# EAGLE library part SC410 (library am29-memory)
ELAN SC410 embedded 486 processor
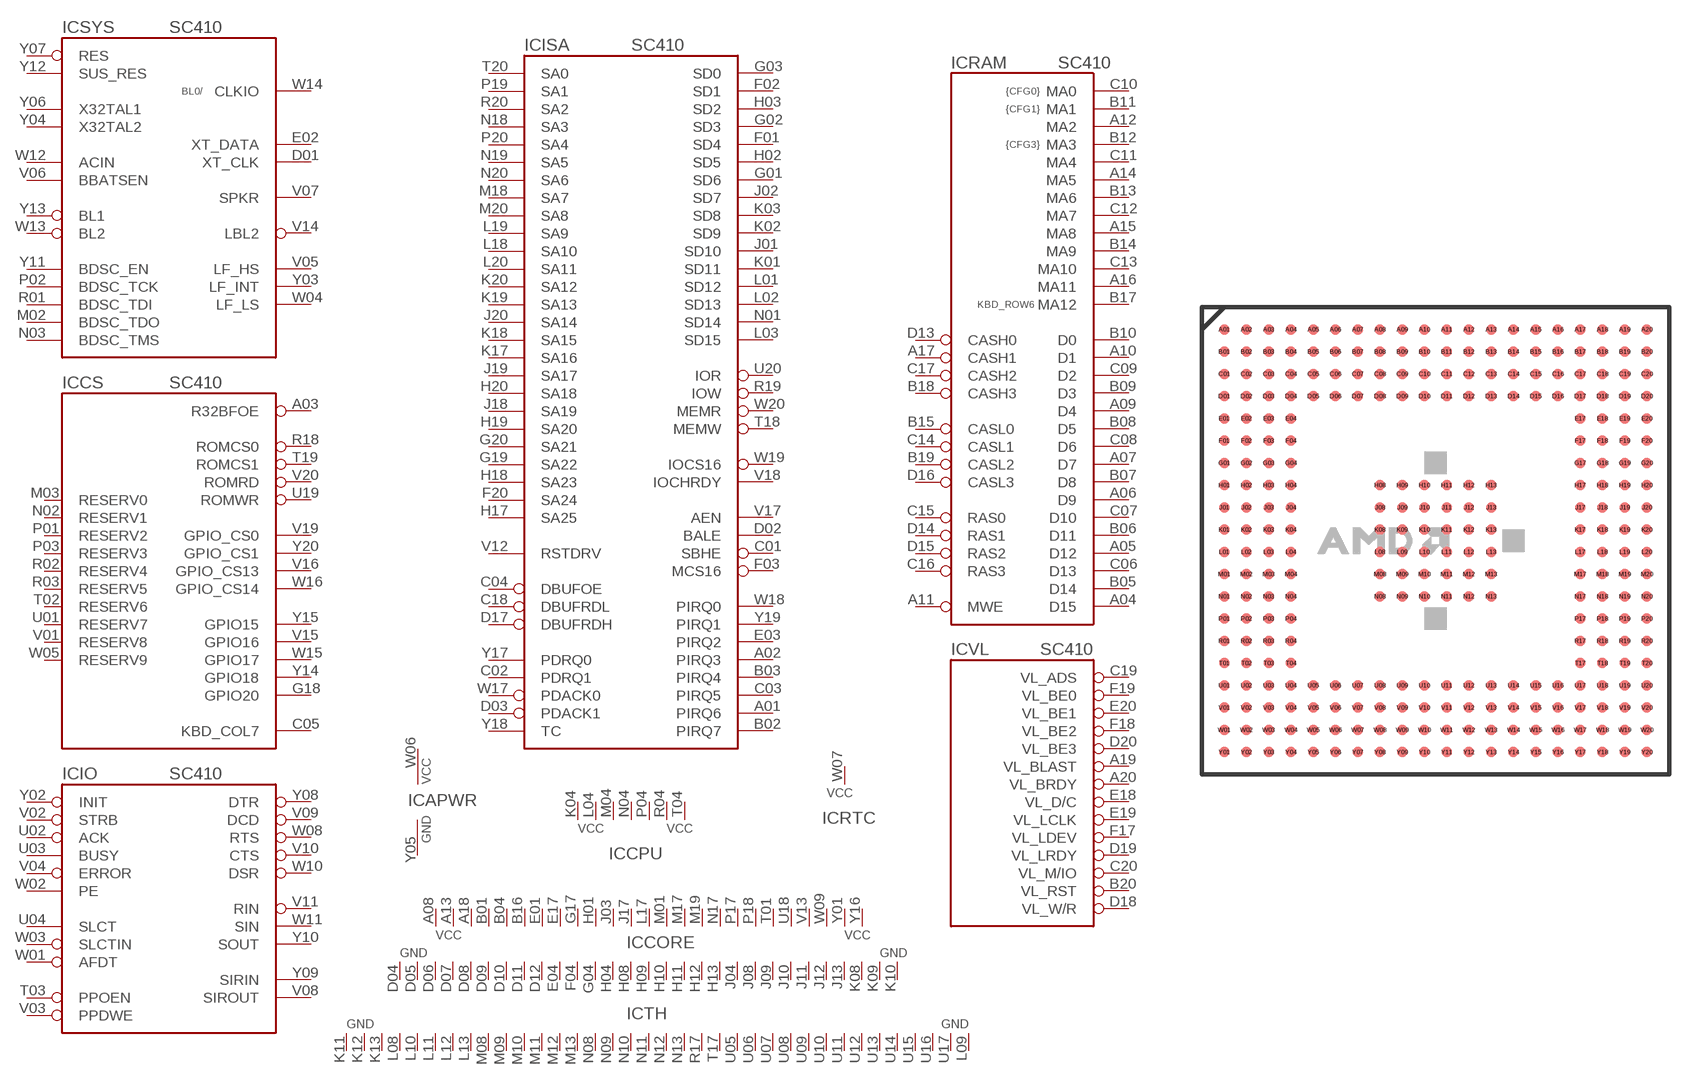
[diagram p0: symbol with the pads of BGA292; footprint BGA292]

Designator prefix IC; gates APWR=APWR CORE=COREPWR CPU=CPUPWR RTC=RTCPWR TH=THERM36 SYS=SYSMGR CS=CHIPSEL IO=SIO_EPP ISA=ISABUS RAM=DRAMBUS VL=VLBUS

## SC410  [BGA292]
A01  ISA:PIRQ6  in
A02  ISA:PIRQ3  in
A03  CS:R32BFOE  out
A04  RAM:D15
A05  RAM:D12
A06  RAM:D9
A07  RAM:D7
A08  CORE:VCC  pwr
A09  RAM:D4
A10  RAM:D1
A11  RAM:MWE  out
A12  RAM:MA2  out
A13  CORE:VCC  pwr
A14  RAM:MA5  out
A15  RAM:MA8  out
A16  RAM:MA11  out
A17  RAM:CASH1  out
A18  CORE:VCC  pwr
A19  VL:VL_BLAST  out
A20  VL:VL_BRDY  out
B01  CORE:VCC  pwr
B02  ISA:PIRQ7  in
B03  ISA:PIRQ4  in
B04  CORE:VCC  pwr
B05  RAM:D14
B06  RAM:D11
B07  RAM:D8
B08  RAM:D5
B09  RAM:D3
B10  RAM:D0
B11  RAM:MA1  out
B12  RAM:MA3  out
B13  RAM:MA6  out
B14  RAM:MA9  out
B15  RAM:CASL0  out
B16  CORE:VCC  pwr
B17  RAM:MA12  out
B18  RAM:CASH3  out
B19  RAM:CASL2  out
B20  VL:VL_RST  out
C01  ISA:SBHE  out
C02  ISA:PDRQ1  in
C03  ISA:PIRQ5  in
C04  ISA:DBUFOE  out
C05  CS:KBD_COL7  out
C06  RAM:D13
C07  RAM:D10
C08  RAM:D6
C09  RAM:D2
C10  RAM:MA0  out
C11  RAM:MA4  out
C12  RAM:MA7  out
C13  RAM:MA10  out
C14  RAM:CASL1  out
C15  RAM:RAS0  out
C16  RAM:RAS3  out
C17  RAM:CASH2  out
C18  ISA:DBUFRDL  out
C19  VL:VL_ADS  out
C20  VL:VL_M/IO  out
D01  SYS:XT_CLK
D02  ISA:BALE  out
D03  ISA:PDACK1  in
D04  CORE:GND  pwr
D05  CORE:GND  pwr
D06  CORE:GND  pwr
D07  CORE:GND  pwr
D08  CORE:GND  pwr
D09  CORE:GND  pwr
D10  CORE:GND  pwr
D11  CORE:GND  pwr
D12  CORE:GND  pwr
D13  RAM:CASH0  out
D14  RAM:RAS1  out
D15  RAM:RAS2  out
D16  RAM:CASL3  out
D17  ISA:DBUFRDH  out
D18  VL:VL_W/R  out
D19  VL:VL_LRDY  out
D20  VL:VL_BE3  out
E01  CORE:VCC  pwr
E02  SYS:XT_DATA
E03  ISA:PIRQ2  in
E04  CORE:GND  pwr
E17  CORE:VCC  pwr
E18  VL:VL_D/C  out
E19  VL:VL_LCLK  out
E20  VL:VL_BE1  out
F01  ISA:SD4
F02  ISA:SD1
F03  ISA:MCS16  out
F04  CORE:GND  pwr
F17  VL:VL_LDEV  out
F18  VL:VL_BE2  out
F19  VL:VL_BE0  out
F20  ISA:SA24  out
G01  ISA:SD6
G02  ISA:SD3
G03  ISA:SD0
G04  CORE:GND  pwr
G17  CORE:VCC  pwr
G18  CS:GPIO20  out
G19  ISA:SA22  out
G20  ISA:SA21  out
H01  CORE:VCC  pwr
H02  ISA:SD5
H03  ISA:SD2
H04  CORE:GND  pwr
H08  CORE:GND  pwr
H09  CORE:GND  pwr
H10  CORE:GND  pwr
H11  CORE:GND  pwr
H12  CORE:GND  pwr
H13  CORE:GND  pwr
H17  ISA:SA25  out
H18  ISA:SA23  out
H19  ISA:SA20  out
H20  ISA:SA18  out
J01  ISA:SD10
J02  ISA:SD7
J03  CORE:VCC  pwr
J04  CORE:GND  pwr
J08  CORE:GND  pwr
J09  CORE:GND  pwr
J10  CORE:GND  pwr
J11  CORE:GND  pwr
J12  CORE:GND  pwr
J13  CORE:GND  pwr
J17  CORE:VCC  pwr
J18  ISA:SA19  out
J19  ISA:SA17  out
J20  ISA:SA14  out
K01  ISA:SD11
K02  ISA:SD9
K03  ISA:SD8
K04  CPU:CPUVCC  pwr
K08  CORE:GND  pwr
K09  CORE:GND  pwr
K10  CORE:GND  pwr
K11  TH:GND  pwr
K12  TH:GND  pwr
K13  TH:GND  pwr
K17  ISA:SA16  out
K18  ISA:SA15  out
K19  ISA:SA13  out
K20  ISA:SA12  out
L01  ISA:SD12
L02  ISA:SD13
L03  ISA:SD15
L04  CPU:CPUVCC  pwr
L08  TH:GND  pwr
L09  TH:GND  pwr
L10  TH:GND  pwr
L11  TH:GND  pwr
L12  TH:GND  pwr
L13  TH:GND  pwr
L17  CORE:VCC  pwr
L18  ISA:SA10  out
L19  ISA:SA9  out
L20  ISA:SA11  out
M01  CORE:VCC  pwr
M02  SYS:BDSC_TDO  in
M03  CS:RESERV0  nc
M04  CPU:CPUVCC  pwr
M08  TH:GND  pwr
M09  TH:GND  pwr
M10  TH:GND  pwr
M11  TH:GND  pwr
M12  TH:GND  pwr
M13  TH:GND  pwr
M17  CORE:VCC  pwr
M18  ISA:SA7  out
M19  CORE:VCC  pwr
M20  ISA:SA8  out
N01  ISA:SD14
N02  CS:RESERV1  nc
N03  SYS:BDSC_TMS  in
N04  CPU:CPUVCC  pwr
N08  TH:GND  pwr
N09  TH:GND  pwr
N10  TH:GND  pwr
N11  TH:GND  pwr
N12  TH:GND  pwr
N13  TH:GND  pwr
N17  CORE:VCC  pwr
N18  ISA:SA3  out
N19  ISA:SA5  out
N20  ISA:SA6  out
P01  CS:RESERV2  nc
P02  SYS:BDSC_TCK  in
P03  CS:RESERV3  nc
P04  CPU:CPUVCC  pwr
P17  CORE:VCC  pwr
P18  CORE:VCC  pwr
P19  ISA:SA1  out
P20  ISA:SA4  out
R01  SYS:BDSC_TDI  in
R02  CS:RESERV4  nc
R03  CS:RESERV5  nc
R04  CPU:CPUVCC  pwr
R17  TH:GND  pwr
R18  CS:ROMCS0  out
R19  ISA:IOW  out
R20  ISA:SA2  out
T01  CORE:VCC  pwr
T02  CS:RESERV6  nc
T03  IO:PPOEN  out
T04  CPU:CPUVCC  pwr
T17  TH:GND  pwr
T18  ISA:MEMW  out
T19  CS:ROMCS1  out
T20  ISA:SA0  out
U01  CS:RESERV7  nc
U02  IO:ACK  in
U03  IO:BUSY  in
U04  IO:SLCT  in
U05  TH:GND  pwr
U06  TH:GND  pwr
U07  TH:GND  pwr
U08  TH:GND  pwr
U09  TH:GND  pwr
U10  TH:GND  pwr
U11  TH:GND  pwr
U12  TH:GND  pwr
U13  TH:GND  pwr
U14  TH:GND  pwr
U15  TH:GND  pwr
U16  TH:GND  pwr
U17  TH:GND  pwr
U18  CORE:VCC  pwr
U19  CS:ROMWR  out
U20  ISA:IOR  out
V01  CS:RESERV8  nc
V02  IO:STRB  out
V03  IO:PPDWE  out
V04  IO:ERROR  in
V05  SYS:LF_HS  out
V06  SYS:BBATSEN  in
V07  SYS:SPKR  out
V08  IO:SIROUT  out
V09  IO:DCD  in
V10  IO:CTS  out
V11  IO:RIN  in
V12  ISA:RSTDRV  out
V13  CORE:VCC  pwr
V14  SYS:LBL2  out
V15  CS:GPIO16  out
V16  CS:GPIO_CS13  out
V17  ISA:AEN  out
V18  ISA:IOCHRDY  in
V19  CS:GPIO_CS0  out
V20  CS:ROMRD  out
W01  IO:AFDT  out
W02  IO:PE  in
W03  IO:SLCTIN  out
W04  SYS:LF_LS  out
W05  CS:RESERV9  nc
W06  APWR:AVCC  pwr
W07  RTC:RTCVCC  pwr
W08  IO:RTS  out
W09  CORE:VCC  pwr
W10  IO:DSR  in
W11  IO:SIN  in
W12  SYS:ACIN  in
W13  SYS:BL2  in
W14  SYS:CLKIO
W15  CS:GPIO17  out
W16  CS:GPIO_CS14  out
W17  ISA:PDACK0  in
W18  ISA:PIRQ0  in
W19  ISA:IOCS16  in
W20  ISA:MEMR  out
Y01  CORE:VCC  pwr
Y02  IO:INIT  out
Y03  SYS:LF_INT  out
Y04  SYS:X32TAL2  in
Y05  APWR:AGND  pwr
Y06  SYS:X32TAL1  in
Y07  SYS:RES  in
Y08  IO:DTR  out
Y09  IO:SIRIN  in
Y10  IO:SOUT  out
Y11  SYS:BDSC_EN  in
Y12  SYS:SUS_RES  in
Y13  SYS:BL1  in
Y14  CS:GPIO18  out
Y15  CS:GPIO15  out
Y16  CORE:VCC  pwr
Y17  ISA:PDRQ0  in
Y18  ISA:TC  out
Y19  ISA:PIRQ1  in
Y20  CS:GPIO_CS1  out

## Footprint BGA292 (pad centres in mm)
Ball Grid Array
smd 0.6 x 0.6: A01 -12.065,12.065; A02 -10.795,12.065; A03 -9.525,12.065; A04 -8.255,12.065; A05 -6.985,12.065; A06 -5.715,12.065; A07 -4.445,12.065; A08 -3.175,12.065; A09 -1.905,12.065; A10 -0.635,12.065; A11 0.635,12.065; A12 1.905,12.065; A13 3.175,12.065; A14 4.445,12.065; A15 5.715,12.065; A16 6.985,12.065; A17 8.255,12.065; A18 9.525,12.065; A19 10.795,12.065; A20 12.065,12.065; B01 -12.065,10.795; B02 -10.795,10.795; B03 -9.525,10.795; B04 -8.255,10.795; B05 -6.985,10.795; B06 -5.715,10.795; B07 -4.445,10.795; B08 -3.175,10.795; B09 -1.905,10.795; B10 -0.635,10.795; B11 0.635,10.795; B12 1.905,10.795; B13 3.175,10.795; B14 4.445,10.795; B15 5.715,10.795; B16 6.985,10.795; B17 8.255,10.795; B18 9.525,10.795; B19 10.795,10.795; B20 12.065,10.795; C01 -12.065,9.525; C02 -10.795,9.525; C03 -9.525,9.525; C04 -8.255,9.525; C05 -6.985,9.525; C06 -5.715,9.525; C07 -4.445,9.525; C08 -3.175,9.525; C09 -1.905,9.525; C10 -0.635,9.525; C11 0.635,9.525; C12 1.905,9.525; C13 3.175,9.525; C14 4.445,9.525; C15 5.715,9.525; C16 6.985,9.525; C17 8.255,9.525; C18 9.525,9.525; C19 10.795,9.525; C20 12.065,9.525; D01 -12.065,8.255; D02 -10.795,8.255; D03 -9.525,8.255; D04 -8.255,8.255; D05 -6.985,8.255; D06 -5.715,8.255; D07 -4.445,8.255; D08 -3.175,8.255; D09 -1.905,8.255; D10 -0.635,8.255; D11 0.635,8.255; D12 1.905,8.255; D13 3.175,8.255; D14 4.445,8.255; D15 5.715,8.255; D16 6.985,8.255; D17 8.255,8.255; D18 9.525,8.255; D19 10.795,8.255; D20 12.065,8.255; E01 -12.065,6.985; E02 -10.795,6.985; E03 -9.525,6.985; E04 -8.255,6.985; E17 8.255,6.985; E18 9.525,6.985; E19 10.795,6.985; E20 12.065,6.985; F01 -12.065,5.715; F02 -10.795,5.715; F03 -9.525,5.715; F04 -8.255,5.715; F17 8.255,5.715; F18 9.525,5.715; F19 10.795,5.715; F20 12.065,5.715; G01 -12.065,4.445; G02 -10.795,4.445; G03 -9.525,4.445; G04 -8.255,4.445; G17 8.255,4.445; G18 9.525,4.445; G19 10.795,4.445; G20 12.065,4.445; H01 -12.065,3.175; H02 -10.795,3.175; H03 -9.525,3.175; H04 -8.255,3.175; H08 -3.175,3.175; H09 -1.905,3.175; H10 -0.635,3.175; H11 0.635,3.175; H12 1.905,3.175; H13 3.175,3.175; H17 8.255,3.175; H18 9.525,3.175; H19 10.795,3.175; H20 12.065,3.175; J01 -12.065,1.905; J02 -10.795,1.905; J03 -9.525,1.905; J04 -8.255,1.905; J08 -3.175,1.905; J09 -1.905,1.905; J10 -0.635,1.905; J11 0.635,1.905; J12 1.905,1.905; J13 3.175,1.905; J17 8.255,1.905; J18 9.525,1.905; J19 10.795,1.905; J20 12.065,1.905; K01 -12.065,0.635; K02 -10.795,0.635; K03 -9.525,0.635; K04 -8.255,0.635; K08 -3.175,0.635; K09 -1.905,0.635; K10 -0.635,0.635; K11 0.635,0.635; K12 1.905,0.635; K13 3.175,0.635; K17 8.255,0.635; K18 9.525,0.635; K19 10.795,0.635; K20 12.065,0.635; L01 -12.065,-0.635; L02 -10.795,-0.635; L03 -9.525,-0.635; L04 -8.255,-0.635; L08 -3.175,-0.635; L09 -1.905,-0.635; L10 -0.635,-0.635; L11 0.635,-0.635; L12 1.905,-0.635; L13 3.175,-0.635; L17 8.255,-0.635; L18 9.525,-0.635; L19 10.795,-0.635; L20 12.065,-0.635; M01 -12.065,-1.905; M02 -10.795,-1.905; M03 -9.525,-1.905; M04 -8.255,-1.905; M08 -3.175,-1.905; M09 -1.905,-1.905; M10 -0.635,-1.905; M11 0.635,-1.905; M12 1.905,-1.905; M13 3.175,-1.905; M17 8.255,-1.905; M18 9.525,-1.905; M19 10.795,-1.905; M20 12.065,-1.905; N01 -12.065,-3.175; N02 -10.795,-3.175; N03 -9.525,-3.175; N04 -8.255,-3.175; N08 -3.175,-3.175; N09 -1.905,-3.175; N10 -0.635,-3.175; N11 0.635,-3.175; N12 1.905,-3.175; N13 3.175,-3.175; N17 8.255,-3.175; N18 9.525,-3.175; N19 10.795,-3.175; N20 12.065,-3.175; P01 -12.065,-4.445; P02 -10.795,-4.445; P03 -9.525,-4.445; P04 -8.255,-4.445; P17 8.255,-4.445; P18 9.525,-4.445; P19 10.795,-4.445; P20 12.065,-4.445; R01 -12.065,-5.715; R02 -10.795,-5.715; R03 -9.525,-5.715; R04 -8.255,-5.715; R17 8.255,-5.715; R18 9.525,-5.715; R19 10.795,-5.715; R20 12.065,-5.715; T01 -12.065,-6.985; T02 -10.795,-6.985; T03 -9.525,-6.985; T04 -8.255,-6.985; T17 8.255,-6.985; T18 9.525,-6.985; T19 10.795,-6.985; T20 12.065,-6.985; U01 -12.065,-8.255; U02 -10.795,-8.255; U03 -9.525,-8.255; U04 -8.255,-8.255; U05 -6.985,-8.255; U06 -5.715,-8.255; U07 -4.445,-8.255; U08 -3.175,-8.255; U09 -1.905,-8.255; U10 -0.635,-8.255; U11 0.635,-8.255; U12 1.905,-8.255; U13 3.175,-8.255; U14 4.445,-8.255; U15 5.715,-8.255; U16 6.985,-8.255; U17 8.255,-8.255; U18 9.525,-8.255; U19 10.795,-8.255; U20 12.065,-8.255; V01 -12.065,-9.525; V02 -10.795,-9.525; V03 -9.525,-9.525; V04 -8.255,-9.525; V05 -6.985,-9.525; V06 -5.715,-9.525; V07 -4.445,-9.525; V08 -3.175,-9.525; V09 -1.905,-9.525; V10 -0.635,-9.525; V11 0.635,-9.525; V12 1.905,-9.525; V13 3.175,-9.525; V14 4.445,-9.525; V15 5.715,-9.525; V16 6.985,-9.525; V17 8.255,-9.525; V18 9.525,-9.525; V19 10.795,-9.525; V20 12.065,-9.525; W01 -12.065,-10.795; W02 -10.795,-10.795; W03 -9.525,-10.795; W04 -8.255,-10.795; W05 -6.985,-10.795; W06 -5.715,-10.795; W07 -4.445,-10.795; W08 -3.175,-10.795; W09 -1.905,-10.795; W10 -0.635,-10.795; W11 0.635,-10.795; W12 1.905,-10.795; W13 3.175,-10.795; W14 4.445,-10.795; W15 5.715,-10.795; W16 6.985,-10.795; W17 8.255,-10.795; W18 9.525,-10.795; W19 10.795,-10.795; W20 12.065,-10.795; Y01 -12.065,-12.065; Y02 -10.795,-12.065; Y03 -9.525,-12.065; Y04 -8.255,-12.065; Y05 -6.985,-12.065; Y06 -5.715,-12.065; Y07 -4.445,-12.065; Y08 -3.175,-12.065; Y09 -1.905,-12.065; Y10 -0.635,-12.065; Y11 0.635,-12.065; Y12 1.905,-12.065; Y13 3.175,-12.065; Y14 4.445,-12.065; Y15 5.715,-12.065; Y16 6.985,-12.065; Y17 8.255,-12.065; Y18 9.525,-12.065; Y19 10.795,-12.065; Y20 12.065,-12.065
